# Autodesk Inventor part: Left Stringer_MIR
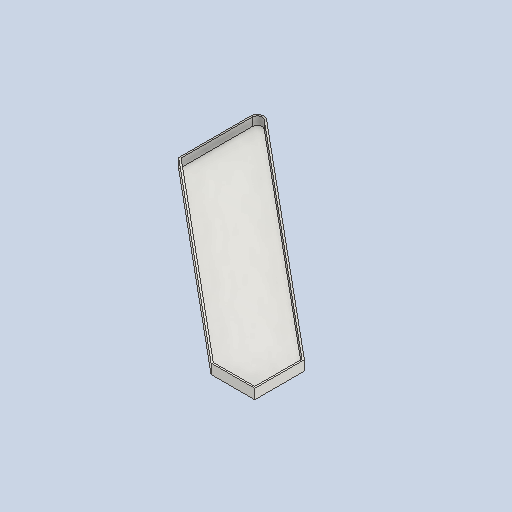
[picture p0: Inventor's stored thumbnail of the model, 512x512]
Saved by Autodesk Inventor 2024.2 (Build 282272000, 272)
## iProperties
Created: 2022-06
Part Number: Left Stringer_MIR
Material: Steel, Galvanized
Document SubType Name: Modeling
Designer: reaumed
Mass: 28099.6 g
Surface Area: 11501.7 cm^2
Volume: 3579.57 cm^3
Density: 7.85 g/cm^3
Appearance: Galvanized
Author: reaumed
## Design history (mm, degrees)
derived "Stringer.ipt"
  sketch "Stringer Profile Sketch"
    geometry: L1 (0, 0)-(914.4, 0) reference; L2 (914.4, 0)-(914.4, -762) reference; L3 (914.4, -762)-(0, -762) reference; L4 (0, -762)-(0, 0) reference; L5 (845.482, -1035.202)-(-68.918, -273.202) reference; L6 (-68.918, -273.202)-(93.689, -78.074) reference; L7 (93.689, -78.074)-(1008.089, -840.074) reference; L8 (1008.089, -840.074)-(845.482, -1035.202) reference; L9 (0, -190.5)-(228.6, -190.5) reference; L10 (0, -190.5)-(0, -330.634) reference; L11 (746.239, -952.5)-(914.4, -952.5) reference; L12 (914.4, -952.5)-(914.4, -762) reference; L13 (0, -1812.658)-(0, 302.11) reference; L14 (2188.973, 0)-(-445.234, 0) reference; L15 (0, -190.5)-(0, -54.23) reference; L16 (93.689, -78.074)-(41.661, -34.717) reference; A1 r 25.4 centre (25.4, -54.23) between (41.661, -34.717) and (0, -54.23) reference; 2 further points
  node "Half the Width Workplane"
feature "Solid2::Stringer.ipt"
tag "TaggingFeature1"
body "Solid2"
